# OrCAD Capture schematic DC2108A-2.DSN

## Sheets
1 PAGE3: size A
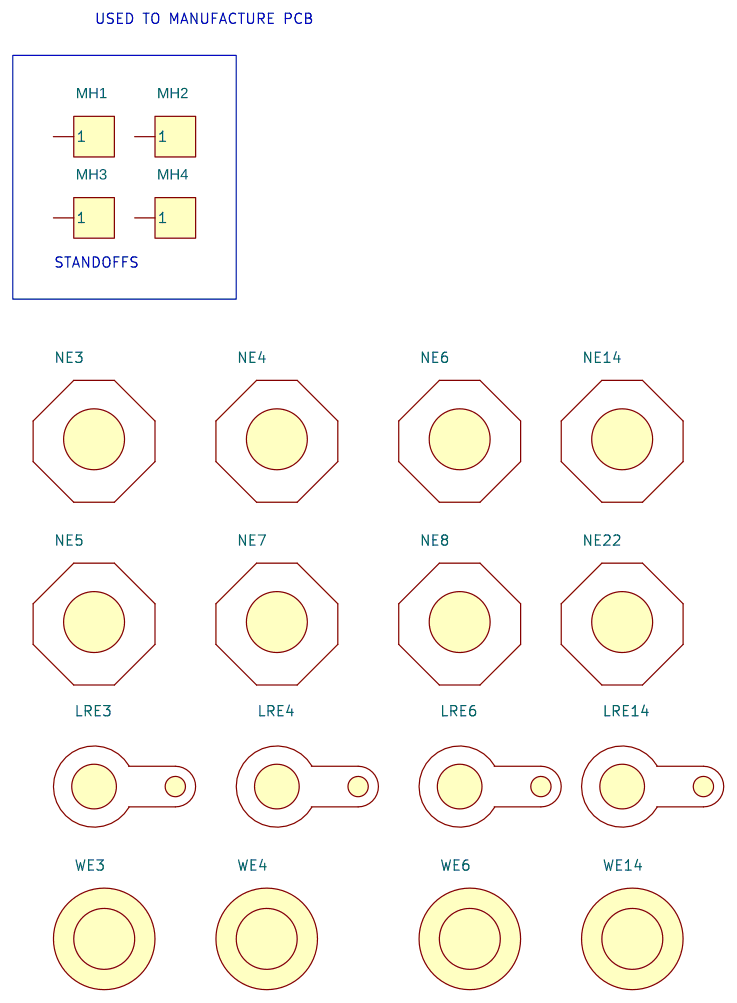
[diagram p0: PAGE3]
2 PAGE2: size A; title: POLYPHASE SYNCHRONOUS BOOST POWER CONVERTER; rev: 2; company: TM; note: WITH INPUT PROTECTION
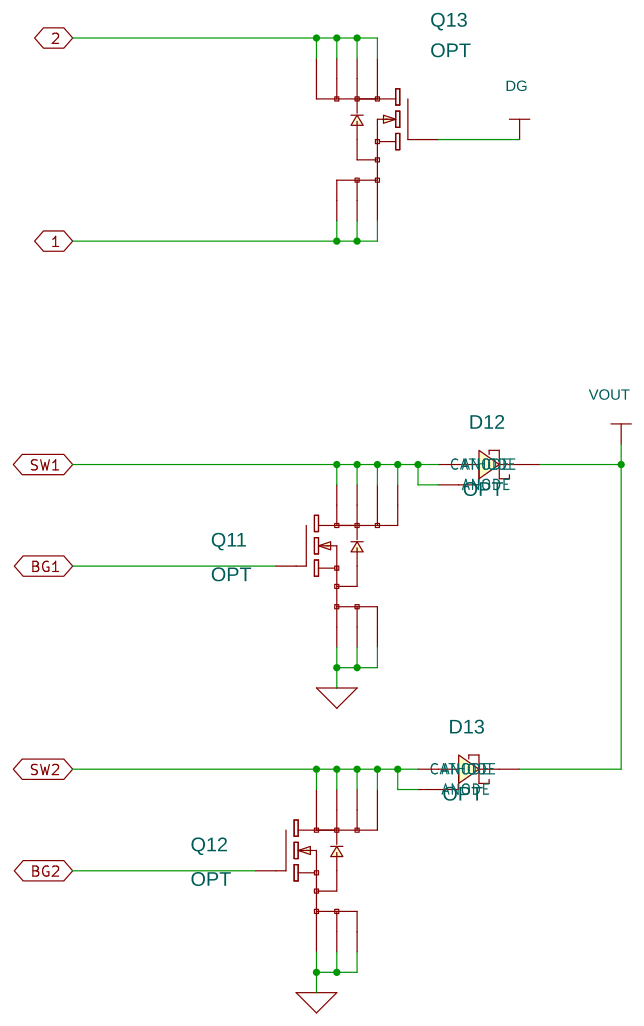
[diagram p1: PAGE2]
3 PAGE1: size Custom; title: POLYPHASE SYNCHRONOUS BOOST POWER CONVERTER; rev: 2; company: TM; note: WITH INPUT PROTECTION
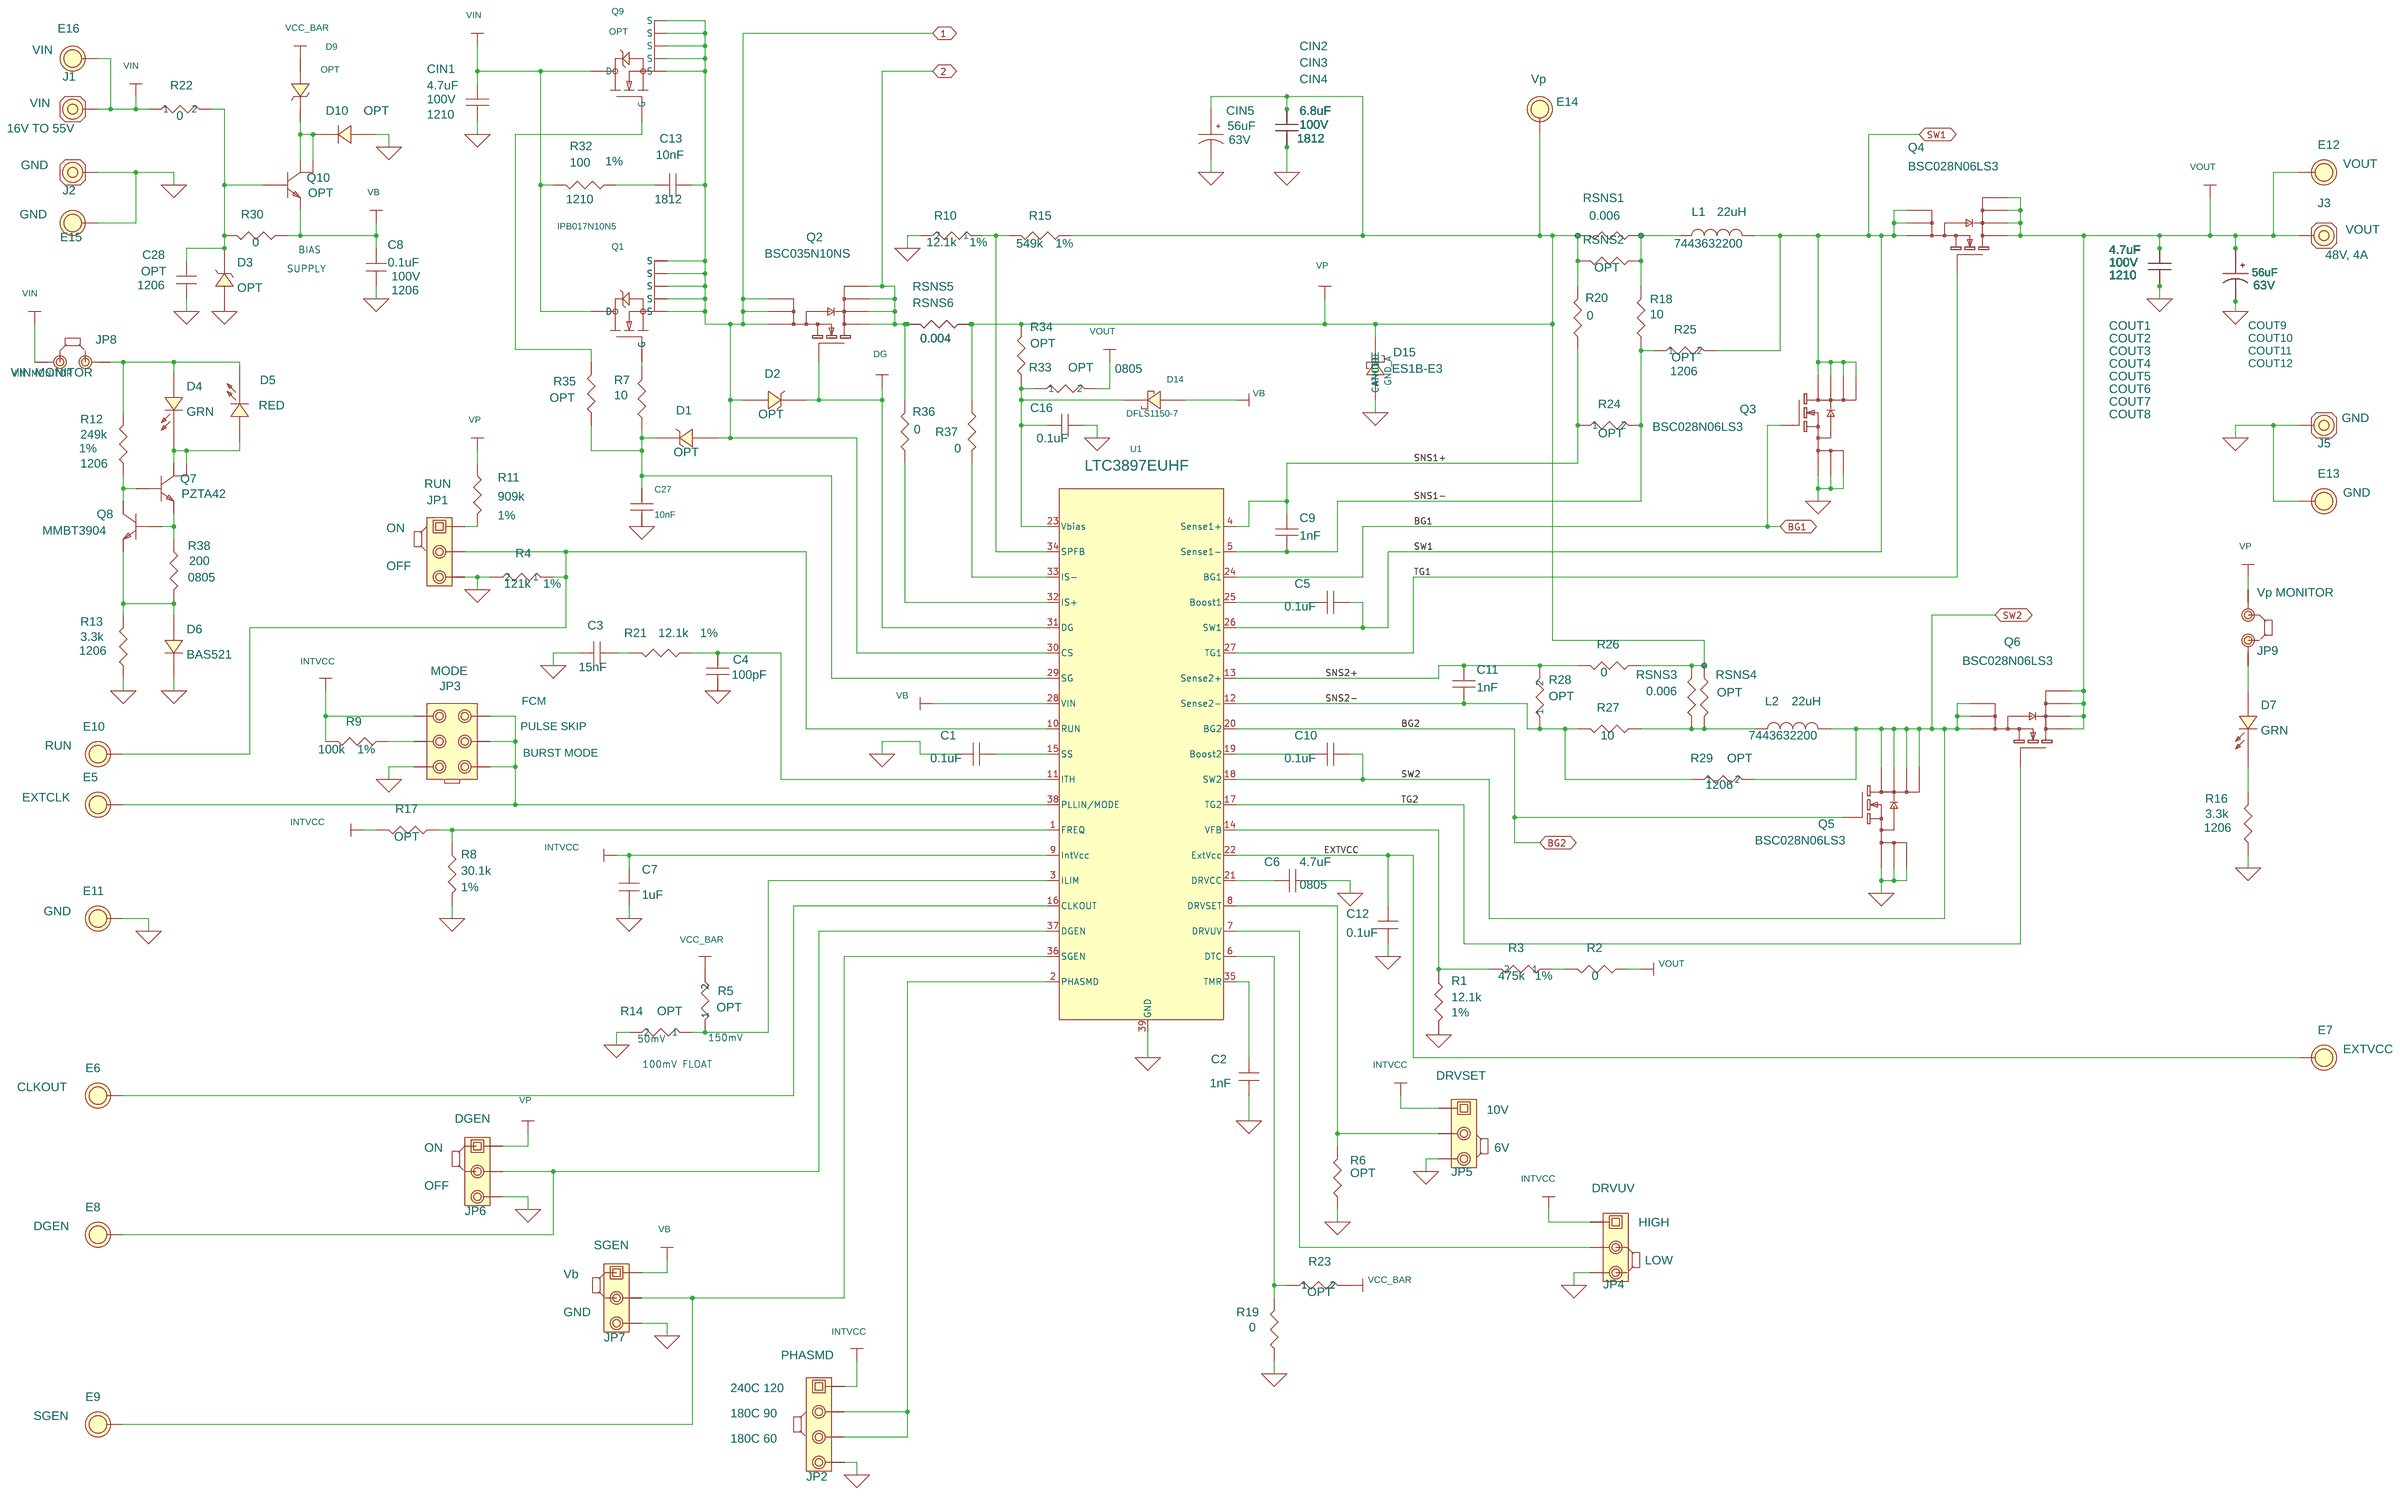
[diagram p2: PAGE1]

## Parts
sheet PAGE1
C1  0.1uF  [0603]
C2  1nF  [0603]
C3  15nF  [0603]
C4  100pF  [0603]
C5  0.1uF  [0603]
C6  4.7uF  [0805]
C7  1uF  [0603]
C8  0.1uF  [1206]
C9  1nF  [0603]
C10  0.1uF  [0603]
C11  1nF  [0603]
C12  0.1uF  [0603]
C13  10nF  [1812]
C16  0.1uF  [0603]
C27  10nF  [0603]
C28  OPT  [1206]
CIN1  4.7uF  [1210]
CIN2  6.8uF  [1812]
CIN3  6.8uF  [1812]
CIN4  6.8uF  [1812]
CIN5  56uF  [CAP\PAN\EEHZA1J560P]
COUT1  4.7uF  [1210]
COUT2  4.7uF  [1210]
COUT3  4.7uF  [1210]
COUT4  4.7uF  [1210]
COUT5  4.7uF  [1210]
COUT6  4.7uF  [1210]
COUT7  4.7uF  [1210]
COUT8  4.7uF  [1210]
COUT9  56uF  [CAP\PAN\EEHZA1J560P]
COUT10  56uF  [CAP\PAN\EEHZA1J560P]
COUT11  56uF  [CAP\PAN\EEHZA1J560P]
COUT12  56uF  [CAP\PAN\EEHZA1J560P]
D1  OPT  [SOD323]
D2  OPT  [SOD323]
D3  OPT  [SMA-DIODE]
D4  GRN  [LED_0603]
D5  RED  [LED_0603]
D6  BAS521  [SOD523]
D7  GRN  [LED_0603]
D9  OPT  [SMA-DIODE]
D10  OPT  [SMA-DIODE]
D14  DFLS1150-7  [POWERDI_123]
D15  ES1B-E3  [PWR_DI-5]
E5  2A  [TP\MMX\2501-2]
E6  3A  [TP\MMX\2501-2]
E7  3A  [TP\MMX\2501-2]
E8  3A  [TP\MMX\2501-2]
E9  3A  [TP\MMX\2501-2]
E10  2A  [TP\MMX\2501-2]
E11  2A  [TP\MMX\2501-2]
E12  3A  [TP\MMX\2501-2]
E13  3A  [TP\MMX\2501-2]
E14  2A  [TP\MMX\2501-2]
E15  3A  [TP\MMX\2501-2]
E16  3A  [TP\MMX\2501-2]
J1  Testpin  [con\lug\10]
J2  Testpin  [con\lug\10]
J3  Testpin  [con\lug\10]
J5  Testpin  [con\lug\10]
JP1  3 Pins 2mm Ctrs.  [SIP\3P\2MM]
JP2  3 Pins 2mm Ctrs.  [SIP\4P\2MM]
JP3  2 Pins 2mm Ctrs.  [HDR\3X2\2MM]
JP4  3 Pins 2mm Ctrs.  [SIP\3P\2MM]
JP5  3 Pins 2mm Ctrs.  [SIP\3P\2MM]
JP6  3 Pins 2mm Ctrs.  [SIP\3P\2MM]
JP7  3 Pins 2mm Ctrs.  [SIP\3P\2MM]
JP8  2 Pins 2mm Ctrs.  [SIP\2P\2MM]
JP9  2 Pins 2mm Ctrs.  [SIP\2P\2MM]
L1  22uH  [IND\WRTH\74435572200]
L2  22uH  [IND\WRTH\74435572200]
Q1  IPB017N10N5  [D2PAK-7]
Q2  BSC035N10NS  [PWRPK_SO8]
Q3  BSC028N06LS3  [PWRPK_SO8]
Q4  BSC028N06LS3  [PWRPK_SO8]
Q5  BSC028N06LS3  [PWRPK_SO8]
Q6  BSC028N06LS3  [PWRPK_SO8]
Q7  PZTA42  [SOT223-FZTXXX]
Q8  MMBT3904  [SOT23]
Q9  OPT  [D2PAK-7]
Q10  OPT  [SOT223-FZTXXX]
R1  12.1k  [0603]
R2  0  [0603]
R3  475k  [0603]
R4  121k  [0603]
R5  OPT  [0603]
R6  OPT  [0603]
R7  10  [0603]
R8  30.1k  [0603]
R9  100k  [0603]
R10  12.1k  [0603]
R11  909k  [0603]
R12  249k  [1206]
R13  3.3k  [1206]
R14  OPT  [0603]
R15  549k  [0603]
R16  3.3k  [1206]
R17  OPT  [0603]
R18  10  [0603]
R19  0  [0603]
R20  0  [0603]
R21  12.1k  [0603]
R22  0  [0603]
R23  OPT  [0603]
R24  OPT  [0603]
R25  OPT  [1206]
R26  0  [0603]
R27  10  [0603]
R28  OPT  [0603]
R29  OPT  [1206]
R30  0  [0603]
R32  100  [1210]
R33  OPT  [0805]
R34  OPT  [0603]
R35  OPT  [0603]
R36  0  [0603]
R37  0  [0603]
R38  200  [0805]
RSNS1  0.006  [2010]
RSNS2  OPT  [2010]
RSNS3  0.006  [2010]
RSNS4  OPT  [2010]
RSNS5  0.004  [2010]
RSNS6  0.004  [2010]
U1  LTC3897EUHF  [LT_UHF38_5X7]
XJP1  2mm Ctrs.
XJP2  2mm Ctrs.
XJP3  2mm Ctrs.
XJP4  2mm Ctrs.
XJP5  2mm Ctrs.
XJP6  2mm Ctrs.
XJP7  2mm Ctrs.
XJP8  2mm Ctrs.
XJP9  2mm Ctrs.
sheet PAGE2
D12  OPT  [PWR_DI-5]
D13  OPT  [PWR_DI-5]
Q11  OPT  [PWRPK_SO8]
Q12  OPT  [PWRPK_SO8]
Q13  OPT  [PWRPK_SO8]
sheet PAGE3
LRE3  Lug_Ring
LRE4  Lug_Ring
LRE6  Lug_Ring
LRE14  Lug_Ring
MH1  CON1  [KEYSTONE_8831]
MH2  CON1  [KEYSTONE_8831]
MH3  CON1  [KEYSTONE_8831]
MH4  CON1  [KEYSTONE_8831]
NE3  NUT
NE4  NUT
NE5  NUT
NE6  NUT
NE7  NUT
NE8  NUT
NE14  NUT
NE22  NUT
WE3  Washer
WE4  Washer
WE6  Washer
WE14  Washer

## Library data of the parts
C1 = CAP_NP: CAP, 0603 0.1uF10% 50V X7R; Case: 1206; Part Number: AVX 06035C104KAT2A; Tolerance: X7R; Voltage: 50V
C2 = CAP0603: CAP, 0603 1nF 10% 50V X7R; Part Number: AVX 06035C102KAT; Tolerance: X7R; Voltage: 50V
C3 = CAP_NP: CAP, 0603 15nF 10% 25V X7R; Case: 1206; FIELD1: 0805; Part Number: AVX 06033C153KAT2A; Tolerance: X7R; Voltage: 25V
C4 = CAP_NP: CAP, 0603 100pF 5% 50V NPO; Case: 0402; FIELD1: 0805; Part Number: AVX 06035A101JAT2A; Tolerance: NPO; Voltage: 50V
C5 C10 C16 = CAP_NP: CAP, 0603 0.1uF10% 50V X7R; Case: 1206; FIELD1: 0805; Part Number: AVX 06035C104KAT2A; Tolerance: X7R; Voltage: 50V
C6 = CAP_NP: CAP, 0805 4.7uF 20& 16V X5R; Case: 1206; Part Number: AVX 0805YD475MAT2A; Tolerance: X5R; Voltage: 16V
C7 = CAP0402: CAP, 0603 1uF 20% 25V X5R; 1ST PART FIELD: 10V; 2ND PART FIELD: 0402; Part Number: AVX 06033D105KAT2A
C8 = CAP0402: CAP, 1206 0.1uF10% 100V X7R; 1ST PART FIELD: 10V; 2ND PART FIELD: 0402; Part Number: MURATA GCM319R72A104KA37D; Voltage: 100V
C9 = CAP_NP: CAP, 0603 1nF 10% 50V X7R; Case: 1206; Part Number: AVX 06035C102KAT; Tolerance: X7R; Voltage: 50V
C11 = CAP_NP: CAP, 0603 1nF 10% 50V X7R; Case: 1206; FIELD1: 0805; Part Number: AVX 06035C102KAT; Tolerance: X7R; Voltage: 50V
C12 = CAP0603: CAP, 0603 0.1uF10% 50V X7R; Part Number: AVX 06035C104KAT2A; Tolerance: X7R; Voltage: 50V
C13 = CAP_NP: CAP, 1812 10nF 5% 630V COG; Case: 1206; FIELD1: 0603; Part Number: TDK C4532C0G2J103J; Tolerance: X7R; Voltage: 50V
C27 = CAP_NP: CAP, 0603 10nF 10% 25V X7R; Part Number: AVX 06033C103KAT2A
C28 = CAP0402: CAP, 1206 OPTION; 1ST PART FIELD: 10V; 2ND PART FIELD: 0402; Part Number: OPTION; Voltage: 100V
CIN1 COUT1-COUT8 = CAP_NP: CAP, 1210 4.7uF 20% 100V X7S; FIELD1: 0805; Part Number: TDK C3225X7S2A475M; Tolerance: X5R; Voltage: 100V
CIN2-CIN4 = CAP_NP: CAP, 1812 6.8uF 10% 100V X7S; Part Number: TDK CKG45NX7S2A685M500JH; Tolerance: X7R; Voltage: 100V
CIN5 = tant_0: CAP, 56uF 20% 63V ELECT; Part Number: PANASONIC EEHZA1J560P / NIPPON CHEMI-CON HHXA630RA560MJA0G; Voltage: 63V
COUT9-COUT12 = tant_3: CAP, 56uF 20% 63V ELECT; Part Number: PANASONIC EEHZA1J560P / NIPPON CHEMI-CON HHXA630RA560MJA0G; Voltage: 63V
D1 D2 = DIODE_ZENER_0: DIODE, OPTION SOD-323; Part Number: DIODES INC. DDZ9702S-7 OPTION
D3 = DIODE_ZENER_0: DIODE, OPTION SMA; Part Number: CENTRAL SEMI CMZ5945B OPTION
D4 D7 = LED_0: LED, GREEN; Part Number: LITE ON LTST-C193KGKT-5A
D5 = LED_0: LED, RED; Part Number: LITE ON LTST-C193KRKT-5A
D6 = DIODE: DIODE, SWITCHING, HIGH VOLTAGE; Part Number: DIODES INC. BAS521
D9 = DIODE_ZENER_0: DIODE, OPTION SMA; Part Number: DIODES INC. SMAJ24A-13 OPTION
D10 = DIODE: DIODE, OPTION SMA; Part Number: DIODES INC. ES1G OPTION
D14 = DIODE_SCHOTTKY_2: DIODE, SCHOTTKY; Part Number: DIODES INC. DFLS1150-7
D15 = DIODE_SCHOTTKY_3: DIODE, SCHOTTKY; Part Number: VISHAY ES1B-E3
E5 = E_4: TURRET; INPUT: EXTCLK; Part Number: MILL-MAX 2501-2-00-80-00-00-07-0; STATUS: 1.6V, 1.8V, 2.0V OR 2.5V @ 15A
E6 = E_4: TURRET; INPUT: CLKOUT; Part Number: MILL-MAX 2501-2-00-80-00-00-07-0; STATUS: 1.6V, 1.8V, 2.0V OR 2.5V @ 15A
E7 = E_4: TURRET; INPUT: EXTVCC; Part Number: MILL-MAX 2501-2-00-80-00-00-07-0; STATUS: 1.6V, 1.8V, 2.0V OR 2.5V @ 15A
E8 = E_4: TURRET; INPUT: DGEN; Part Number: MILL-MAX 2501-2-00-80-00-00-07-0; STATUS: 1.6V, 1.8V, 2.0V OR 2.5V @ 15A
E9 = E_4: TURRET; INPUT: SGEN; Part Number: MILL-MAX 2501-2-00-80-00-00-07-0; STATUS: 1.6V, 1.8V, 2.0V OR 2.5V @ 15A
E10 = E_4: TURRET; INPUT: RUN; Part Number: MILL-MAX 2501-2-00-80-00-00-07-0; STATUS: 1.6V, 1.8V, 2.0V OR 2.5V @ 15A
E11 E13 E15 = E_4: TURRET; INPUT: GND; Part Number: MILL-MAX 2501-2-00-80-00-00-07-0; STATUS: 1.6V, 1.8V, 2.0V OR 2.5V @ 15A
E12 = E_4: TURRET; INPUT: VOUT; Part Number: MILL-MAX 2501-2-00-80-00-00-07-0; STATUS: 1.6V, 1.8V, 2.0V OR 2.5V @ 15A
E14 = E_4: TURRET; INPUT: Vp; Part Number: MILL-MAX 2501-2-00-80-00-00-07-0; STATUS: 1.6V, 1.8V, 2.0V OR 2.5V @ 15A
E16 = E_4: TURRET; INPUT: VIN; Part Number: MILL-MAX 2501-2-00-80-00-00-07-0; STATUS: 1.6V, 1.8V, 2.0V OR 2.5V @ 15A
J1 = PEM-kfh-032-10: STUD, TESTPIN; 10th Part Field: 16V TO 55V; 9th Part Field: VIN; Part Number: PEM KFH-032-10
J2 J5 = PEM-kfh-032-10: STUD, TESTPIN; 10th Part Field: 5 - 24V #; 9th Part Field: GND; Part Number: PEM KFH-032-10
J3 = PEM-kfh-032-10: STUD, TESTPIN; 10th Part Field: 48V, 4A; 9th Part Field: VOUT; Part Number: PEM KFH-032-10
JP1 = Samtec_TMM-103-02-L-S: HEADER, 3PIN, 2mm; 11th Part Field: OFF; 12th Part Field: RUN; 9th Part Field: ON; Part Number: SULLINS, NRPN031PAEN-RC
JP2 = Samtec_TMM-103-02-L-S_0: HEADER, 4PIN, 2mm; 11th Part Field: 180C 90; 12th Part Field: PHASMD; 4th Part Field: 180C 60; 5th Part Field: ON1_CONTROL; 9th Part Field: 240C 120; Part Number: SULLINS, NRPN041PAEN-RC
JP3 = Samtec_TMM-: HEADER, 3PIN, DBL ROW 2mm; 4th Part Field: FCM; 5th Part Field: PULSE SKIP; 7th Part Field: BURST MODE; 9th Part Field: MODE; Part Number: SULLINS, NRPN032PAEN-M456RC
JP4 = Samtec_TMM-103-02-L-S: HEADER, 3PIN, 2mm; 11th Part Field: LOW; 12th Part Field: DRVUV; 9th Part Field: HIGH; Part Number: SULLINS, NRPN031PAEN-RC
JP5 = Samtec_TMM-103-02-L-S: HEADER, 3PIN, 2mm; 11th Part Field: 6V; 12th Part Field: DRVSET; 9th Part Field: 10V; Part Number: SULLINS, NRPN031PAEN-RC
JP6 = Samtec_TMM-103-02-L-S: HEADER, 3PIN, 2mm; 11th Part Field: OFF; 12th Part Field: DGEN; 9th Part Field: ON; Part Number: SULLINS, NRPN031PAEN-RC
JP7 = Samtec_TMM-103-02-L-S: HEADER, 3PIN, 2mm; 11th Part Field: GND; 12th Part Field: SGEN; 9th Part Field: Vb; Part Number: SULLINS, NRPN031PAEN-RC
JP8 = Samtec_TMM-102-02-L-S_1: HEADER, SINGLE ROW, 2 PIN, 2mm; 9th Part Field: VIN MONITOR; Part Number: SULLINS, NRPN021PAEN-RC
JP9 = Samtec_TMM-102-02-L-S: HEADER, SINGLE ROW, 2 PIN, 2mm; 9th Part Field: Vp MONITOR; Part Number: SULLINS, NRPN021PAEN-RC
L1 L2 = INDUCTOR: IND, 22uH; 10th Part Field: 7443632200; Part Number: WURTH 7443632200; manufacturing: WURTH
Q1 = IRLS3034-7PPbF: XSTR, POWER MOSFET; Part Number: INFINEON IPB017N10N5 / INTERMATIONAL RECTIFIER IRLS3034-7PPbF
Q2 = 2N7002_2: XSTR, POWER MOSFET; Part Number: INFINEON BSC035N10NS
Q3-Q6 = 2N7002_2: XSTR, POWER MOSFET; Part Number: INFINEON BSC028N06LS3
Q7 = MMBTA42L_0: XSTR, NPN HIGH VOLTAGE AMP; Part Number: FAIRCHILD PZTA42
Q8 = MMBT3904_SOT_0: XSTR, NPN SMALL SIGNAL; Part Number: FAIRCHILD. MMBT3904
Q9 = IRLS3034-7PPbF: XSTR, OPTION; Part Number: OPTION
Q10 = MMBTA42L_0: XSTR, OPTION; Part Number: FAIRCHILD PZTA42 OPTION
R1 = RESISTOR: RES, 0603 12.1k OHMS 1% 1/10W; Part Number: VISHAY CRCW060312K1FKEA; Tol: 1%
R2 = RESISTOR: RES, 0603 0 OHM JUMPER; Part Number: VISHAY CRCW06030000Z0EA; Tolerance: 1%
R3 = R_5: RES, 0603 475k OHMS 1% 1/10W; 5%: 1%; Part Number: VISHAY CRCW0603475KFKEA; Tol: 1%
R4 = R_1: RES, 0603 121k OHMS 1% 1/10W; 5%: 1%; Part Number: VISHAY CRCW0603121KFKEA; Tol: 1%
R5 = R_7: RES, 0603 OPTION; 5%: 1%; Part Number: OPTION
R6 = RESISTOR: RES, 0603 OPTION; Part Number: OPTION; Tolerance: 1%
R7 R18 R27 = AAC-0402: RES, 0603 10 OHMS 1% 1/10W; 4TH PART FIELD: AAC,; Part Number: VISHAY CRCW060310R0FKEA
R8 = RESISTOR: RES, 0603 30.1k OHMS 1% 1/10W; Part Number: VISHAY CRCW060330K1FKEA; Tol: 1%
R9 = RESISTOR: RES, 0603 100k OHMS 1% 1/10W; Part Number: VISHAY CRCW0603100KFKEA; Tol: 1%
R10 = R_11: RES, 0603 12.1k OHMS 1% 1/10W; 5%: 1%; Part Number: VISHAY CRCW060312K1FKEA; Tol: 1%
R11 = AAC-0402: RES, 0603 909k OHMS 1% 1/10W; 4TH PART FIELD: AAC,; Part Number: VISHAY CRCW0603909KFKEA; Tolerance: 1%
R12 = AAC-0402: RES, 1206 249k OHMS 1% 1/4W; 2ND PART FIELD: 1%; 4TH PART FIELD: AAC,; Part Number: VISHAY CRCW1206249KFKEA
R13 R16 = AAC-0402: RES, 1206 3.3k OHMS 5% 1/4W; 2ND PART FIELD: 1%; 4TH PART FIELD: AAC,; Part Number: VISHAY CRCW12063K30JNEA
R14 = R_6: RES, 0603 OPTION; 5%: 1%; Part Number: OPTION
R15 = RESISTOR: RES, 0603 549k OHMS 1% 1/10W; Part Number: VISHAY CRCW0603549KFKEA; Tol: 1%
R17 R34 R35 = AAC-0402: RES, 0603 OPTION; 4TH PART FIELD: AAC,; Part Number: OPTION
R19 R20 R26 R30 R36 R37 = AAC-0402: RES, 0603 0 OHM JUMPER; 4TH PART FIELD: AAC,; Part Number: VISHAY CRCW06030000Z0EA
R21 = AAC-0402: RES, 0603 12.1k OHMS 1% 1/10W; 4TH PART FIELD: AAC,; Part Number: VISHAY CRCW060312K1FKEA; Tol: 1%
R22 = R_8: RES, 0603 0 OHM JUMPER; 5%: 1%; Part Number: VISHAY CRCW06030000Z0EA
R23 = R_10: RES, 0603 OPTION; 5%: 1%; Part Number: OPTION
R24 = R_9: RES, 0603 OPTION; 5%: 1%; Part Number: OPTION
R25 = R_2: RES, 1206 OPTION; 5%: 1%; Part Number: OPTION
R28 = R_4: RES, 0603 OPTION; 5%: 1%; Part Number: OPTION
R29 = R: RES, 1206 OPTION; 5%: 1%; Part Number: OPTION
R32 = RESISTOR: RES, 1210 100 OHMS 1% 1/4W; Part Number: VISHAY CRCW1210100RFKEA; Tol: 1%
R33 = R_3: RES, 0805 OPTION; 5%: 1%; Part Number: OPTION
R38 = AAC-0402: RES, 0805 200 OHMS 5% 1/8W; 2ND PART FIELD: 1%; 4TH PART FIELD: AAC,; Part Number: VISHAY CRCW0805200RJNEA
RSNS1 RSNS3 = R_1: RES, 2010 0.006 OHM 1% 1/2W; %: 0.1%; Part Number: VISHAY WSL20106L000FEA
RSNS2 RSNS4 = R_1: RES, 2010 OPTION; %: 0.1%; Part Number: OPTION
RSNS5 RSNS6 = R_1: RES, 2010 0.004 OHM 1% 0.5W; %: 1%; Part Number: VISHAY  WSL20104L000FEA
U1 = LTC3897EUHF: IC, POLYPHASE SYNCHRONOUS BOOST CONTROLLER; Part Number: LINEAR TECH. LTC3897EUHF
XJP1 XJP2 XJP4-XJP9 = Samtec_2SN-BK-G: SHUNT, 2mm; Part Number: SAMTEC 2SN-BK-G
XJP3 = Samtec_2SN-BK-G_0: SHUNT, 2mm; Part Number: SAMTEC 2SN-BK-G
D12 D13 = DIODE_SCHOTTKY_0: DIODE SCHOTTKY OPTION; Part Number: OPTION
Q11 Q12 = 2N7002_2: XSTR, POWER MOSFET OPTION; Part Number: OPTION
Q13 = 2N7002_2: XSTR, OPTION; Part Number: INFINEON BSC060N10 OPTION
LRE3 LRE4 LRE6 LRE14 = Lug_Ring: LUG RING, #10; Part Number: KEYSTONE 8205
MH1-MH4 = CON1: STANDOFF, SNAP ON; Part Number: KEYSTONE 8834
NE3-NE8 NE14 NE22 = NUT: NUT, BRASS 10-32; Part Number: ANY #10-32
WE3 WE4 WE6 WE14 = Washer: WASHER, #10 TIN PLATED BRASS; Part Number: ANY #10 EXT BZ TN

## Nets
GND_A: C1.1 C2.2 C3.1 C4.2 C6.2 C7.2 C8.2 C12.2 C16.2 C27.2 C28.2 CIN1.2 CIN2.2 CIN3.2 CIN4.2 CIN5.2 COUT1.2 COUT2.2 COUT3.2 COUT4.2 COUT5.2 COUT6.2 COUT7.2 COUT8.2 COUT9.2 COUT10.2 COUT11.2 COUT12.2 D3.2(ANODE) D6.1(K) D10.2(A) D15.2(ANODE) D15.3(GND_A) E11.1(A) E13.1(A) E15.1(A) J2.1 J5.1 JP1.3 JP2.4 JP3.5 JP4.3 JP5.3 JP6.3 JP7.3 Q3.1 Q3.2 Q3.3 Q5.1 Q5.2 Q5.3 Q11.1 Q11.2 Q11.3 Q12.1 Q12.2 Q12.3 R1.2 R4.2 R6.1 R8.1 R10.2 R13.1 R14.2 R16.1 R19.1 U1.39(GND)
VIN: CIN1.1 D9.2(ANODE) E16.1(A) J1.1 JP8.2 Q1.4(D) Q9.4(D) R22.1 R32.1
1: C13.2 D1.2(ANODE) D2.2(ANODE) Q1.2(S) Q1.3(S) Q1.5(S) Q1.6(S) Q1.7(S) Q2.1 Q2.2 Q2.3 Q9.2(S) Q9.3(S) Q9.5(S) Q9.6(S) Q9.7(S) Q13.1 Q13.2 Q13.3 U1.30(CS)
2: Q2.5 Q2.6 Q2.7 Q2.8 Q13.5 Q13.6 Q13.7 Q13.8 R36.2 RSNS5.2 RSNS6.2
BG1: Q3.4 Q11.4 U1.24(BG1)
BG2: Q5.4 Q12.4 U1.20(BG2)
DG: D2.1(CATHODE) Q2.4 Q13.4 U1.31(DG)
EXTVCC: C12.1 E7.1(A) U1.22(ExtVcc)
INTVCC: C7.1 JP2.1 JP3.1 JP4.1 JP5.1 R5.2 R9.1 R17.1 R23.2 U1.9(IntVcc)
SNS1+: C9.1 R20.1 R24.1 U1.4(Sense1+)
SNS1-: C9.2 R18.1 R24.2 R25.1 U1.5(Sense1-)
SNS2+: C11.1 R26.1 R28.2 U1.13(Sense2+)
SNS2-: C11.2 R27.1 R28.1 R29.1 U1.12(Sense2-)
SW1: C5.2 D12.2(ANODE) D12.3(ANODE) L1.1 Q3.5 Q3.6 Q3.7 Q3.8 Q4.1 Q4.2 Q4.3 Q11.5 Q11.6 Q11.7 Q11.8 R25.2 U1.26(SW1)
SW2: C10.2 D13.2(ANODE) D13.3(ANODE) L2.2 Q5.5 Q5.6 Q5.7 Q5.8 Q6.1 Q6.2 Q6.3 Q12.5 Q12.6 Q12.7 Q12.8 R29.2 U1.18(SW2)
TG1: Q4.4 U1.27(TG1)
TG2: Q6.4 U1.17(TG2)
Vb: C8.1 D14.2(ANODE) JP7.1 Q10.3(EMITTER) R30.1 U1.28(VIN)
VOUT: COUT1.1 COUT2.1 COUT3.1 COUT4.1 COUT5.1 COUT6.1 COUT7.1 COUT8.1 COUT9.1 COUT10.1 COUT11.1 COUT12.1 D12.1(CATHODE) D13.1(CATHODE) E12.1(A) J3.1 Q4.5 Q4.6 Q4.7 Q4.8 Q6.5 Q6.6 Q6.7 Q6.8 R2.1 R33.2
Vp: CIN2.1 CIN3.1 CIN4.1 CIN5.1 D15.1(CATHODE) E14.1(A) JP6.1 JP9.2 R11.1 R15.2 R20.2 R26.2 R34.2 R37.2 RSNS1.2 RSNS2.2 RSNS3.2 RSNS4.2 RSNS5.1 RSNS6.1
N16900884: JP1.1 R11.2
N16903619: JP2.2 JP2.3 U1.2(PHASMD)
N17273468: E6.1(A) U1.16(CLKOUT)
N17273839: R5.1 R14.1 U1.3(ILIM)
N17275954: R8.2 R17.2 U1.1(FREQ)
N17277379: E5.1(A) JP3.2 JP3.4 JP3.6 U1.38(PLLIN/MODE)
N17279448: JP3.3 R9.2
N17282539: C1.2 U1.15(SS)
N17283929: C4.1 R21.1 U1.11(ITH)
N17286140: C3.2 R21.2
N17289965: E10.1(A) JP1.2 R4.1 U1.10(RUN)
N17300068: C27.1 D1.1(CATHODE) R7.1 R35.1 U1.29(SG)
N17301219: R36.1 U1.32(IS+)
N17304272: R37.1 U1.33(IS-)
N17307629: R10.1 R15.1 U1.34(SPFB)
N17307894: C16.1 D14.1(CATHODE) R33.1 R34.1 U1.23(Vbias)
N17342925: C5.1 U1.25(Boost1)
N17356442: L2.1 R27.2 RSNS3.1 RSNS4.1
N17363604: C10.1 U1.19(Boost2)
N17367610: JP4.2 U1.7(DRVUV)
N17368879: R1.1 R3.2 U1.14(VFB)
N17370687: R19.2 R23.1 U1.6(DTC)
N17375648: C2.1 U1.35(TMR)
N17379297: C6.1 U1.21(DRVCC)
N17382393: JP5.2 R6.2 U1.8(DRVSET)
N17406470: R2.2 R3.1
N17549317: E8.1(A) JP6.2 U1.37(DGEN)
N17556378: E9.1(A) JP7.2 U1.36(SGEN)
N17565797: C28.1 D3.1(CATHODE) Q10.1(BASE) R22.2 R30.2
N17586669: D4.2(ANODE) D5.1(CATHODE) JP8.1 R12.2
N17625228: D4.1(CATHODE) D5.2(ANODE) Q7.2(COLLECTOR) Q7.4(COLLECTOR)
N17626960: Q7.1(BASE) Q8.3(C) R12.1
N17628263: Q7.3(EMITTER) Q8.1(B) R38.2
N17651259: D7.2(ANODE) JP9.1
N17652005: D7.1(CATHODE) R16.2
N17700697: L1.2 R18.2 RSNS1.1 RSNS2.1
N17813801: D9.1(CATHODE) D10.1(K) Q10.2(COLLECTOR) Q10.4(COLLECTOR)
N17898191: C13.1 R32.2
N18084157: Q1.1(G) R7.2
N18084703: Q9.1(G) R35.2
N18125266: D6.2(A) Q8.2(E) R13.2 R38.1

Not connected (* = marked no-connect by the designer): MH1 1; MH2 1; MH3 1; MH4 1

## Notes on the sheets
sheet 1
- USED TO MANUFACTURE PCB
- STANDOFFS
sheet 3
- BIAS
- SUPPLY
- VIN MONITOR
- 50mV
- 150mV
- 100mV FLOAT
